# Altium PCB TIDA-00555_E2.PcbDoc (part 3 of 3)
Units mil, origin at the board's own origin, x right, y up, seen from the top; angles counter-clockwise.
Board outline 6490 x 3985 mil, 4 copper layers (Top Layer, MidLayer1, MidLayer2, Bottom Layer), stack 61.2 mil thick; 376 components, 194 nets, 936 pads, 294 vias.
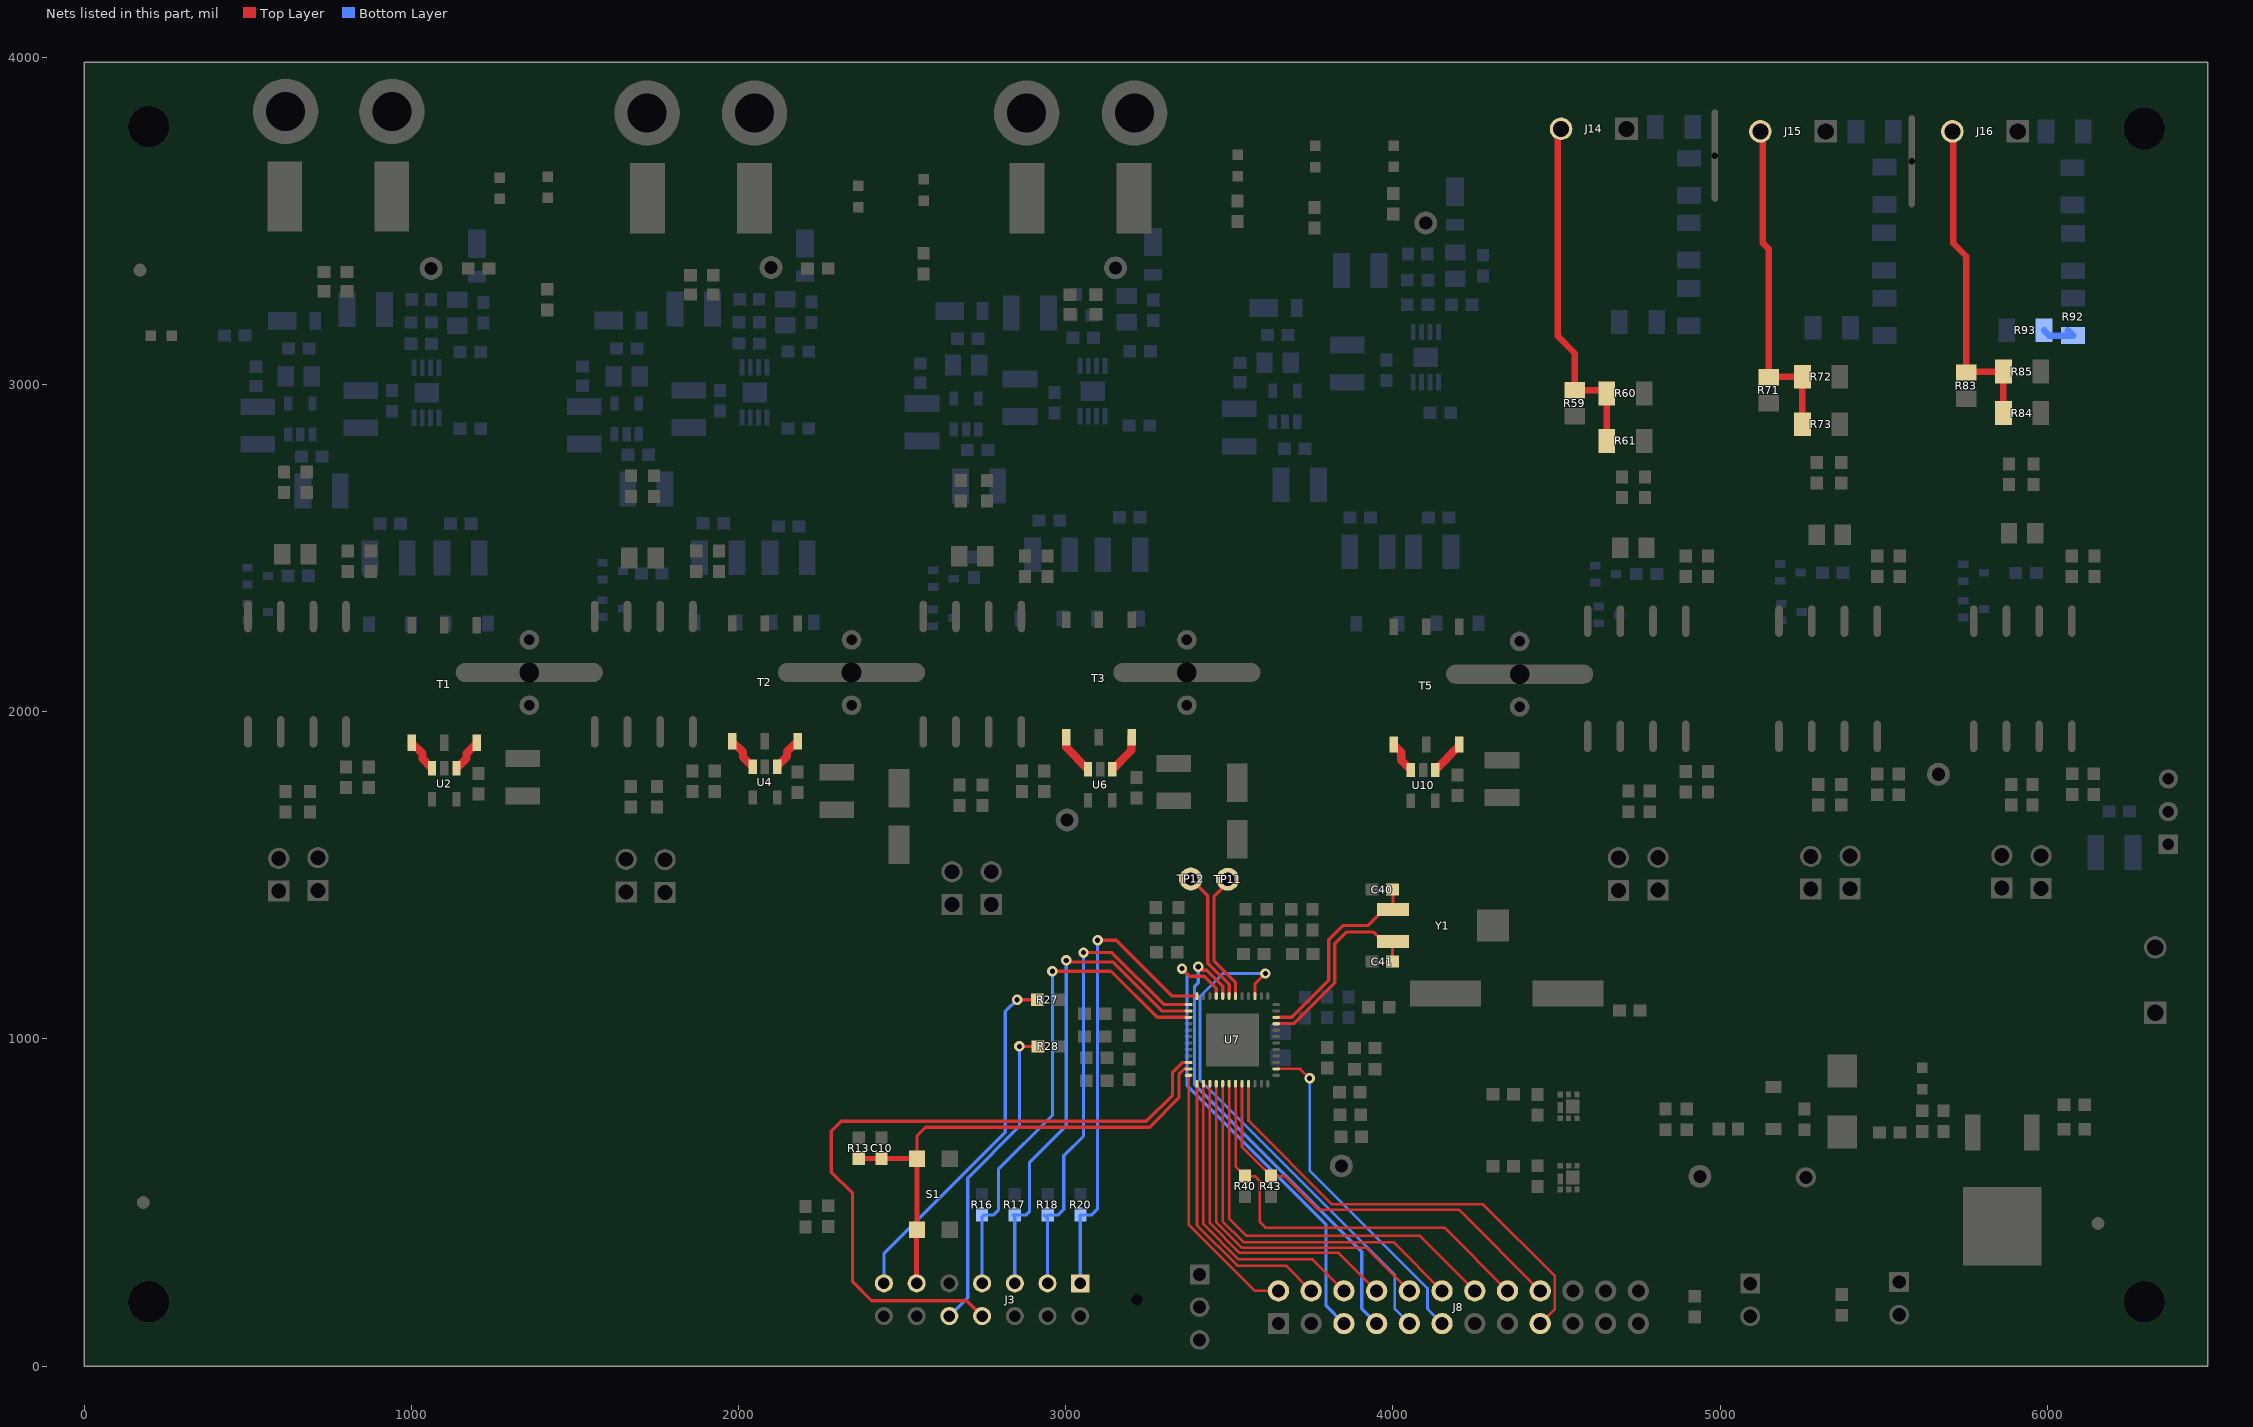
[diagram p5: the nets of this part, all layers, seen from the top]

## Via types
v1: diameter 32, hole 16, Top Layer to Bottom Layer, tented both sides, 177 vias
v2: diameter 40, hole 20, Top Layer to Bottom Layer, tented both sides, 109 vias
v3: diameter 19.68, hole 7.87, Top Layer to Bottom Layer, tented both sides, 8 vias

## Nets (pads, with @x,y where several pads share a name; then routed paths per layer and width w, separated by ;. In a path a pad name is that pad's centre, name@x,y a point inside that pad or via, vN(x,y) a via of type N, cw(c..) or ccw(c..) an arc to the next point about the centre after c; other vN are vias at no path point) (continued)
NetR92_2: R92.2 R93.1 | length 118.3
  Bottom Layer w20: R93.1@5990.09,3166 6006.17,3149.91 R92.2@6079,3149.91 R92.2@6062.91,3166
NetT1_1: T1.1 U2.3 | length 103.7
  Top Layer w25: T1.1@1000,1905 1033,1872 1033,1856.84 U2.3@1062.6,1827.24
NetT1_3: T1.3 U2.1 | length 103.7
  Top Layer w25: U2.1@1137.4,1827.24 1168,1857.84 1168,1873 T1.3@1200,1905
NetT2_1: T2.1 U4.3 | length 103.7
  Top Layer w25: T2.1@1980,1910 2013,1877 2013,1861.84 U4.3@2042.6,1832.24
NetT2_3: T2.3 U4.1 | length 103.7
  Top Layer w25: U4.1@2117.4,1832.24 2148,1862.84 2148,1878 T2.3@2180,1910
NetT3_1: T3.1 U6.3 | length 125.8
  Top Layer w25: T3.1@3000,1922 3000,1891.84 U6.3@3067.6,1824.24
NetT3_3: T3.3 U6.1 | length 121.6
  Top Layer w25: U6.1@3142.4,1824.24 3200,1881.84 T3.3@3200,1922
NetT5_1: T5.1 U10.3 | length 99.5
  Top Layer w25: T5.1@4002,1900.22 4025,1877.22 4025,1852.07 U10.3@4054.6,1822.47
NetT5_3: T5.3 U10.1 | length 107.8
  Top Layer w25: U10.1@4129.4,1822.47 4202,1895.07 T5.3@4202,1900.22
NetTP11_1: TP11.1 U7.6 | length 398.7
  Top Layer w10: TP11.1@3500,1483 3453,1436 3453,1238.17 3518.84,1172.33 U7.6@3518.84,1131.01
NetTP12_1: TP12.1 U7.7 | length 406.5
  Top Layer w10: TP12.1@3382,1489 3434,1437 3434,1231.71 3499.16,1166.56 U7.7@3499.16,1131.01
NEUTRAL: J14.2 J15.2 J16.2 R59.1 R60.1 R61.1 R71.1 R72.1 R73.1 R83.1 R84.1 R85.1 | length 3053.5
  Top Layer w20: J14.2@4513.72,3782 4503.72,3772 4503.72,3148.28 4555.72,3096.28 R59.1@4555.72,2983 4643.64,2983 R60.1@4653.64,2973 R61.1@4653.64,2828 ; J15.2@5122.72,3774 5129.72,3767 5129.72,3434 5148.72,3415 R71.1@5148.72,3023 5149.72,3024 R72.1@5251.64,3024 R73.1@5251.64,2879 ; J16.2@5709.72,3749 5712.72,3746 5712.72,3432 5752,3392.72 R83.1@5752,3037 5755,3040 R85.1@5865.91,3040 R84.1@5865.91,2913
P1.2: J8.9 U7.3 | length 1576.4
  Top Layer w10: U7.3@3577.9,1131.01 3577.9,1167.9 v1(3610,1200)
  Bottom Layer w8: v1(3610,1200) 3480,1200 3410,1130 3410,874 4005.52,278.48 4005.52,174.48 J8.9@4050,130
P1.3: J8.5 U7.9 | length 1443.7
  Top Layer w10: v1(3355,1215) 3378.18,1191.82 3422.99,1191.82 3459.79,1155.02 U7.9@3459.79,1131.01
  Bottom Layer w10: v1(3355,1215) 3370,1200 3370,858 3795.48,432.52 3795.48,184.52 J8.5@3850,130
P2.0: J8.2 U7.24 | length 814.7
  Top Layer w8: U7.24@3375.14,888.88 3375.14,795 3375.14,433.23 3578.37,230 J8.2@3650,230
P2.1: J8.4 U7.25 | length 865.2
  Top Layer w8: U7.25@3400.73,863.29 3400.73,430.27 3524,307 3673,307 J8.4@3750,230
P2.2: J8.6 U7.26 | length 943.5
  Top Layer w8: U7.26@3420.42,863.29 3420.42,433.7 3528.12,326 3754,326 J8.6@3850,230
P2.7: J8.11 U7.38 | length 1031.7
  Top Layer w8: U7.38@3642.86,908.57 3716.43,908.57 v1(3745,880)
  Bottom Layer w8: v1(3745,880) 3745,597.9 4105.52,237.38 4105.52,174.48 J8.11@4150,130
P3.4: J8.8 U7.27 | length 1022.1
  Top Layer w8: U7.27@3440.1,863.29 3440.1,436.64 3530.75,346 3834,346 J8.8@3950,230
P3.5: J8.10 U7.28 | length 1100.7
  Top Layer w8: U7.28@3459.79,863.29 3459.79,439.59 3537.37,362 3918,362 J8.10@4050,230
P3.6: J8.12 U7.29 | length 1179.3
  Top Layer w8: U7.29@3479.47,863.29 3479.47,442.53 3543,379 4001,379 J8.12@4150,230
P3.7: J8.14 U7.30 | length 1254.8
  Top Layer w8: U7.30@3499.16,863.29 3500,862.45 3500,450 3551,399 4081,399 J8.14@4250,230
P4.4: J8.17 U7.33 | length 1410
  Top Layer w8: U7.33@3558.21,863.29 3558.21,750 3814,494.21 4275.79,494.21 4494.48,275.52 4494.48,174.48 J8.17@4450,130
P4.7: J8.7 U7.8 | length 1456.5
  Top Layer w10: v1(3405,1221) 3405,1220 3415.18,1209.82 3430.44,1209.82 3479.47,1160.79 U7.8@3479.47,1131.01
  Bottom Layer w10: v1(3405,1221) 3405,1172.13 3393,1160.13 3393,861 3904.52,349.48 3904.52,175.48 J8.7@3950,130
RESET: C10.1 J3.11 R13.1 S1.1 S1.2 U7.23 | length 1590.9
  Top Layer w10: S1.1@2545,637 2545,704 2571,730 3256,730 3345.55,819.55 3345.55,891.45 3362.67,908.57 U7.23@3375.14,908.57
  Top Layer w15: R13.1@2366.76,634.24 C10.1@2436.76,634.24 S1.1@2548.03,634.24 ; J3.11@2543,254 J3.11@2544,253 2544,415.73 S1.2@2545,416.73 2545,631.2 S1.1@2548.03,634.24 ; S1.1@2549,633.27 S1.1@2548.03,634.24
SCL: J8.18 R43.2 U7.32 | length 1287.6
  Top Layer w8: U7.32@3538.53,863.29 3538.53,668.97 R43.2@3627,580.5 3668.5,580.5 3770.79,478.21 4201.79,478.21 J8.18@4450,230
SDA: J8.16 R40.2 U7.31 | length 1315.3
  Top Layer w8: U7.31@3518.84,863.29 3518.84,609.65 R40.2@3548,580.5 3577.5,580.5 3593,565 3593,440 3610,423 4157,423 J8.16@4350,230
TCK: J3.7 R16.2 U7.15 | length 1535
  Top Layer w10: v1(2959,1207) 3138,1207 3278.95,1066.05 U7.15@3375.14,1066.05
  Bottom Layer w10: J3.7@2744,253 2744,456.5 2749,461.5 2778.7,461.5 2794,476.8 2794,601 2959,766 v1(2959,1207)
TDI: J3.3 R18.2 U7.13 | length 1465.4
  Top Layer w10: v1(3054,1264) 3141,1264 3299.58,1105.42 U7.13@3375.14,1105.42
  Bottom Layer w10: R18.2@2934,461.5 2944,451.5 J3.3@2944,253 ; R18.2@2945,462 2977,462 2994,479 2994,643 3054,703 v1(3054,1264)
TDO: J3.1 R20.2 U7.12 | length 1466
  Top Layer w10: v1(3097,1302) 3154.01,1302 3325,1131.01 U7.12@3400.73,1131.01
  Bottom Layer w10: J3.1@3044,253 3044,460.5 R20.2@3045,461.5 3077.5,461.5 3097,481 v1(3097,1302) v1@3096,1301
TEST/SBWTCK: J3.8 U7.22 | length 2146.3
  Top Layer w10: J3.8@2744,153 2697,200 2406,200 2348,258 2348,528 2283,593 2283,718 2313,748 3246,748 3326.33,828.33 3326.33,897.67 3356.9,928.25 U7.22@3375.14,928.25
TMS: J3.5 R17.2 U7.14 | length 1516.8
  Top Layer w10: v1(3001,1240) 3006,1235 3144.54,1235 3293.81,1085.73 U7.14@3375.14,1085.73
  Bottom Layer w10: J3.5@2844,253 2844,456.5 2839,461.5 2877.5,461.5 2889,473 2889,623 3001,735 v1(3001,1240)
UART_CTS: J3.10 R28.1 | length 969.1
  Top Layer w10: v1(2858,977) R28.1@2914.5,977
  Bottom Layer w10: J3.10@2644,153 2700,209 2700,574.51 2858,732.51 v1(2858,977)
UART_RTS: J3.13 R27.1 | length 1097.1
  Top Layer w10: v1(2851,1120) R27.1@2912.5,1120
  Bottom Layer w10: J3.13@2444,253 2444,343.96 2815,714.96 2815,1084 v1(2851,1120)
XIN: C41.1 U7.45 Y1.2 | length 617.1
  Top Layer w10: U7.45@3642.86,1046.36 3643.5,1047 3697.01,1047 3822.23,1172.22 3822.23,1291.23 3858,1327 3940,1327 3969.66,1297.34 Y1.2@4000.26,1297.34 3998.61,1295.68 C41.1@3998.61,1236.55
XOUT: C40.1 U7.46 Y1.1 | length 627.8
  Top Layer w10: U7.46@3642.86,1066.05 3690.59,1066.05 3804,1179.45 3804,1303 3848,1347 3925,1347 3973.76,1395.76 Y1.1@4000.26,1395.76 4000.26,1454.9 C40.1@3998.61,1456.55
pads on no net: FID1.1 FID2.1 FID3.1 FID4.1 FID5.1 FID6.1 J3. J3.6 J8.1 J8.3 J8.13 J8.15 J8.19 J8.20 LBL1.0 MH1.1 MH2.1 MH3.1 MH4.1 T1.5 T2.5 T3.5 T5.5 U15.7 U16.4 U16.5 U19.7 U20.4 U20.5 U21.7 U22.4 U22.5 U23.7 U24.4 U24.5
copper on no net: | length 6498
  Top Layer w8: 535,110 535,210 ; 635,110 635,210 ; 735,110 735,210 ; 435,110 435,210 835,210 835,110 435,110
  MidLayer1 w8: 435,110 835,110 ; 435,110 435,210 ; 435,110 435,210 ; 435,110 835,110 ; 435,210 835,210 ; 435,210 835,210 ; 835,110 835,210 ; 835,110 835,210 ; 535,110 535,210 535,110 ; 635,110 635,210 635,110 ; 735,110 735,210 735,110
  MidLayer2 w8: 535,110 535,210 ; 635,110 635,210 ; 735,112 735,210 ; 435,110 835,110 835,210 435,210 435,110
  Bottom Layer w8: 535,110 535,210 ; 635,110 635,210 ; 735,110 735,210 ; 435,110 835,110 835,210 435,210 435,110

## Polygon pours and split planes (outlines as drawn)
GND_PH on MidLayer1 "Bottom Layer-No Net 1" (solid, remove dead copper, pour order 118): 3651,2254 3490,2415 3490,3125 3680,3315 3680,3865 3740,3925 4267,3925 4319,3878 4318,3879 4318.24,3925 4318.24,3142.76 4366,3095 6480,3095 6478.24,2270 6460.4,2254
GND_WSH on MidLayer1 "Top Layer-No Net" (solid, remove dead copper, pour order 88): 2535,3375 2430,3270 2430,2415 2560,2285 3340,2285 3342,2287 3342,2290 3341.81,3241.81 3415,3315 3515,3315 3610,3410 3610,3905 3600,3915 3505,3915 3495,3905 3495,3445 3460,3410 2970,3410 2935,3445 2935,3720 2975,3760 2975,3905 2940,3940 2590,3940 2535,3885
GND_VSH on MidLayer1 "Top Layer-No Net" (solid, remove dead copper, pour order 84): 1400,2605 1500,2505 1500,2345 1570,2275 2315,2275 2320,2280 2320,3250 2455,3385 2455,3925 2440,3940 2345,3940 2335,3930 2335,3450 2300,3415 1810,3415 1785,3440 1785,3705 1840,3760 1840,3910 1808.24,3941.76 1446.76,3941.76 1400,3895
GND_USH on MidLayer1 "Top Layer-No Net" (solid, remove dead copper, pour order 80): 130,3940 75,3885 75,2365 170,2270 1305,2270 1330,2295 1330,3910 1310,3930 1230,3930 1215,3915 1215,3440 1195,3420 715,3420 665,3470 665,3710 725,3770 725,3900 685,3940
DGND on MidLayer1 "Bottom Layer-No Net 1" (solid, remove dead copper, pour order 98): 20,1870 125,1975 6333,1975 6422,1886 6422,107 6335,20 180,20 20,180
NEUTRAL on MidLayer1 "Bottom Layer-No Net 1" (solid, remove dead copper, pour order 119): 4408.2,3930.2 4448,3970 6015,3970 6025,3960 6025,3850 6013,3837 5813.45,3836.95 5777,3800.5 5777,3591.97 5735.53,3550.5 5651.65,3550.5 5618,3584.15 5618,3843 5593,3868 5269.5,3868 5227,3825.5 5227,3575.5 5202,3550.5 5052,3550.5 5032,3570.5 5032,3842 4999,3875 4676.5,3875 4627,3825.5 4627,3600.5 4577,3550.5 4433,3550 4410,3550 4408.2,3550.5
+5.0V_PH on MidLayer2 "Bottom Layer-No Net 1" (solid, remove dead copper, pour order 117): 3650,2255 3490,2415 3490,3120 3680,3310 3680,3860 3740,3920 4265,3920 4318,3867 4318,3192 4319,3145 4343,3121 4363.71,3097.29 4391,3097 6478.98,3097 6478.23,2255
+5.0V_WSH on MidLayer2 "Top Layer-No Net" (solid, remove dead copper, pour order 87): 2540,3370 2435,3265 2435,2410 2560,2285 3345,2285 3347,2287 3347,2294 3346.81,3236.81 3420,3310 3520,3310 3615,3405 3615,3900 3605,3910 3510,3910 3500,3900 3500,3440 3465,3405 2975,3405 2940,3440 2940,3715 2980,3755 2980,3900 2945,3935 2595,3935 2540,3880
+5.0V_VSH on MidLayer2 "Top Layer-No Net" (solid, remove dead copper, pour order 83): 1400,2600 1500,2500 1500,2345 1570,2275 2290,2275 2320,2305.11 2320,3245 2455,3380 2455,3920 2440,3935 2345,3935 2335,3925 2335,3445 2300,3410 1810,3410 1785,3435 1785,3700 1840,3755 1840,3905 1808.24,3936.76 1446.76,3936.76 1400,3890
+5.0V_USH on MidLayer2 "Top Layer-No Net" (solid, remove dead copper, pour order 79): 130,3940 75,3885 75,2395 200,2270 1305,2270 1330,2295 1330,3910 1310,3930 1230,3930 1215,3915 1215,3440 1195,3420 715,3420 665,3470 665,3710 725,3770 725,3900 685,3940
AVCC on MidLayer2 "Top Layer-No Net" (solid, remove dead copper, pour order 70): 6405,1630 6441.76,1593.24 6441.76,1302.35 6399.41,1260 5760,1260 5710,1210 5710.2,689.02 5670,650 4594.18,650 4174.18,1020 130,1020 60,1090 60,1570 120,1630
DVCC on MidLayer2 "Bottom Layer-No Net 1" (solid, remove dead copper, pour order 100): 135,20 20,135 20,875 120,975 4125,975 4485,615 5690,615 5749,674 5749,1159 5785,1195 6390,1195 6415,1170 6415,20
AMC_VCC on MidLayer2 "Top Layer-No Net" (solid, remove dead copper, pour order 73): 6422,1660.47 6440,1670 6440,1950 6420,1970 120,1970 60,1910 60,1720 120,1660
+5.0V_PH on Bottom Layer "Bottom Layer-No Net 2" (solid, remove dead copper, pour order 133): 4254,3370 4254,3470 4273.2,3489.2 4273.2,3493.48 4315.52,3493.48 4350,2570 4350,2500 4370,2520 6004,2520 6079,2445 6079,2295 6004,2220 4579,2220 4350,2460 4354,3320 4304,3370
+5V_CNTL on Bottom Layer "Top Layer-No Net" (solid, remove dead copper, pour order 69): 6420,1970 6440,1950 6440,1024.72 6400,984.72 5975.28,984.72 5950,1010 5950,1300 5905,1345 75,1345 50,1370 50,1890 135,1975
AGND on Bottom Layer "Bottom Layer-No Net 2" (solid, remove dead copper, pour order 120): 5880,1295 5895,1280 5895,700 5900,695 6470,695 6470,65 6430,25 144.94,20 20,144.94 25,1295
+6V_PH on Bottom Layer "Bottom Layer-No Net 1" (solid, remove dead copper, pour order 95): 3837.32,2202.15 3897.32,2202.15 3897,2381 3897,2650 3890,2657 3813,2657 3807,2651 3807,2621 3798,2612 3692.32,2612.15 3677.32,2627.15 3677.32,2822.15 3667.32,2832.15 3622.32,2832.15 3612.32,2812.15 3612.32,2562.15 3647.32,2522.15 3707.32,2522.15 3827.32,2397.15 3827.32,2217.15
+6V_WSH on Bottom Layer "Bottom Layer-No Net 1" (solid, remove dead copper, pour order 74): 2861.98,2261 2876.98,2246 2927.98,2246 2940.98,2262 2941.61,2331 2942,2467 2942,2614 2940,2616 2866,2616 2865,2615 2861.61,2611 2851.61,2601 2756.61,2601 2716.61,2641 2716.61,2811 2701.61,2826 2701.61,2871 2681.61,2871 2681.61,2831 2626.61,2776 2626.61,2631 2726.61,2531 2806.61,2531 2861.61,2491 2861.61,2341
+6V_VSH on Bottom Layer "Bottom Layer-No Net 1" (solid, remove dead copper, pour order 75): 1828,2256 1843,2241 1896,2241 1910,2255 1910,2610 1847,2610 1828,2596 1722.64,2596 1682.64,2636 1682.64,2806 1667.64,2821 1667.64,2866 1647.64,2866 1647.64,2826 1592.64,2771 1592.64,2626 1678.64,2540 1796.62,2540 1827.64,2517.45 1827.64,2336
GND_WSH on Bottom Layer "Bottom Layer-No Net 1" (solid, remove dead copper, pour order 91): 2976.61,2406 3136.61,2406 3156.61,2426 3156.61,2646 3141.61,2661 2971.61,2661 2961.61,2651 2961.61,2421
GND_VSH on Bottom Layer "Bottom Layer-No Net 1" (solid, remove dead copper, pour order 92): 1940,2415 2100,2415 2120,2435 2120,2655 2105,2670 1935,2670 1925,2660 1925,2430
GND_USH on Bottom Layer "Bottom Layer-No Net 1" (solid, remove dead copper, pour order 93): 960,2415 1120,2415 1140,2435 1140,2655 1125,2670 955,2670 945,2660 945,2430
+6V_USH on Bottom Layer "Bottom Layer-No Net 1" (solid, remove dead copper, pour order 96): 825,2248 835,2240 910,2240 920,2249 920,2625 845,2625 840,2620 840,2600 835,2595 735,2595 690,2640 690,2790 670,2810 670,2865 665,2870 646.65,2870 646.65,2831.65 645,2830 645,2805 600,2760 600,2615 685,2530 760,2530 825,2465
-5.0V_WSH on Bottom Layer "Bottom Layer-No Net 1" (solid, remove dead copper, pour order 112): 3082,3250 3072,3260 3072,3380 3072,3390 3097,3415 3099,3417 3160,3417 3172,3417 3183,3406 3188,3401 3188,3376 3188,3368 3196,3360 3200,3356 3244,3356 3282,3356 3288,3350 3296,3342 3296,3285 3296,3255 3278,3237 3276,3235 3120,3235 3098,3235 3082,3251
-5.0V_USH on Bottom Layer "Bottom Layer-No Net 1" (solid, remove dead copper, pour order 111): 1035,3290 1005,3320 1005,3390 1040,3425 1115,3425 1130,3410 1130,3370 1145,3355 1225,3355 1275,3300 1275,3250 1250,3225 1050,3225 1035,3232.31
-6V_VSH on Bottom Layer "Bottom Layer-No Net 1" (solid, remove dead copper, pour order 78): 2168,2259 2185,2243 2255,2243 2273,2254.33 2273,2301 2272.64,2336 2272.64,2741 2217.64,2796 2087.64,2796 2082.64,2831 2037.64,2836 2017.64,2866 2017.64,2921 2002.64,2936 1797.64,2936 1772.64,2911 1772.64,2826 1837.64,2736 2142.64,2736 2162.64,2721 2162.64,2716 2167.64,2711 2167.64,2346
NetD37_1 on Bottom Layer "Bottom Layer-No Net 1" (solid, remove dead copper, pour order 89): 1960,2240 1960,2300 1971,2311 1971,2314 2110,2314 2116,2308 2120,2304 2120,2269 2120,2242 2112,2234 2108,2230 1970,2230 1960,2240
-6V_USH on Bottom Layer "Bottom Layer-No Net 1" (solid, remove dead copper, pour order 94): 1181,2232 1284,2232 1323,2268 1321,2579 1286,2614 1270,2631 1270,2765 1230,2805 1041,2805 1015,2831 1015,2925 1000,2940 910,2940 880,2910 790,2910 775,2895 775,2835 855,2755 1160,2755 1185,2730 1185,2635 1160,2610 1160,2335 1180,2306.57
GND_VSH on Bottom Layer "Bottom Layer-No Net 1" (solid, remove dead copper, pour order 102): 1472.64,2846 1562.64,2846 1577.64,2846 1582.64,2841 1582.64,2791 1582.64,2726 1572.64,2716 1487.64,2716 1482.64,2716 1472.64,2726 1472.64,2846
GND_USH on Bottom Layer "Bottom Layer-No Net 1" (solid, remove dead copper, pour order 103): 475,2845 565,2845 580,2845 585,2840 585,2790 585,2725 575,2715 490,2715 485,2715 475,2725 475,2845
GND_USH on Bottom Layer "Bottom Layer-No Net 1" (solid, remove dead copper, pour order 97): 745,2615 746.72,2613.28 816.2,2613.28 816.2,2736.72 815,2737.92 815,2755 815,2760 755,2820 750,2825 750,2855 750,2910 785,2945 795,2955 950,2955 1000,2955 1010,2945 1015,2940 1080,2940 1120,2940 1155,2975 1235,2975 1250,2975 1280,3005 1290,3015 1290,3145 1290,3185 1260,3215 1150,3215 1110,3215 1105,3210 1100,3205 1100,3170 1100,3161 1115,3146 1180,3146 1184,3146 1190,3140 1195,3135 1195,3090 1195,3080 1175,3060 1170,3055 1115,3055 1095,3075 1055,3075 1050,3070 1050,3025 1050,3020 1045,3015 960,3015 895,3015 860,3050 855,3055 855,3265 855,3275 835,3295 730,3295 700,3295 680,3275 665,3260 665,3080 665,2995 680,2980 685,2975 705,2975 710,2975 720,2965 721.03,2963.97 721.03,2885.16 720.16,2885.16 715,2880 695,2880 690,2880 688.29,2878.29 688.29,2870 688.29,2831.71 690,2830 710,2810 710,2770 710,2650 745,2615
GND_VSH on Bottom Layer "Bottom Layer-No Net 1" (solid, remove dead copper, pour order 85): 1737.64,2626 1798.84,2626 1802.64,2631 1802.64,2760.98 1747.64,2815.98 1747.64,2936 1767.64,2956 2137.64,2956 2147.64,2966 2262.64,2966 2302.64,3006 2302.64,3181 2272.64,3211 2117.64,3211 2107.64,3201 2107.64,3166 2122.64,3151 2187.64,3151 2197.64,3141 2197.64,3071 2192.64,3066 2122.64,3066 2102.64,3086 2052.64,3086 2052.64,3026 2037.64,3011 1882.64,3011 1852.64,3041 1852.64,3276 1832.64,3296 1767.64,3296 1757.64,3286 1757.64,3251 1732.64,3226 1682.64,3226 1672.64,3216 1672.64,2891 1682.64,2881 1682.64,2826 1707.64,2801 1707.64,2656
-5.0V_VSH on Bottom Layer "Bottom Layer-No Net 1" (solid, remove dead copper, pour order 113): 2045,3244 2035,3254 2035,3374 2035,3384 2060,3409 2062,3411 2123,3411 2135,3411 2146,3400 2151,3395 2151,3370 2151,3362 2159,3354 2163,3350 2207,3350 2245,3350 2251,3344 2259,3336 2259,3279 2259,3249 2241,3231 2239,3229 2083,3229 2061,3229 2045,3245
NetD21_1 on Bottom Layer "Bottom Layer-No Net 1" (solid, remove dead copper, pour order 115): 3971.5,2236 3971.5,2311 3981.5,2321 3986.5,2326 4076.5,2326 4144,2326 4156.5,2313.5 4156.5,2246 4156.5,2231 4146.5,2221 3986.5,2221 3971.5,2236
GND_PH on Bottom Layer "Bottom Layer-No Net 1" (solid, remove dead copper, pour order 108): 3955,2439 4090,2439 4130,2479 4130,2719 4117.05,2737 3937.05,2737 3925.05,2717 3925,2679 3925,2469
GND_PH on Bottom Layer "Bottom Layer-No Net 1" (solid, remove dead copper, pour order 99): 3475,2839 3565,2839 3580,2839 3585,2834 3585,2784 3585,2719 3575,2709 3490,2709 3485,2709 3475,2719 3475,2839
GND_PH on Bottom Layer "Bottom Layer-No Net 1" (solid, remove dead copper, pour order 110): 3752.95,2629 3725,2649 3725,2774 3710,2794 3710,2829 3700,2849 3700,2894 3727.95,2894 3722.94,3144 3767.95,3144 3767.95,2899 3822.95,2834 3822.95,2639 3812.95,2629
-6V_PH on Bottom Layer "Bottom Layer-No Net 1" (solid, remove dead copper, pour order 90): 4230,2199 4310,2199 4305,2349 4255,2399 4255,2814 4220,2834 4080,2834 4055,2859 4055,2919 4070,2974 4070,3029 3805,3029 3795,2974 3795,2899 3935,2754 4130,2754 4150,2734 4150,2354 4230,2274.8
-5.0V_PH on Bottom Layer "Bottom Layer-No Net 1" (solid, remove dead copper, pour order 114): 4081.2,3454.48 4077.2,3458.48 4077.2,3515.48 4077.2,3517.48 4087.2,3527.48 4089.2,3529.48 4151.2,3529.48 4170.2,3529.48 4200.2,3499.48 4206.2,3493.48 4268.2,3493.48 4273.2,3493.48 4290.2,3476.48 4302.2,3464.48 4302.2,3383.48 4302.2,3380.48 4293.2,3371.48 4292.2,3370.48 4100.2,3370.48 4100.2,3371.48 4087.2,3384.48 4087.2,3440.48 4087.2,3448.48 4081.2,3454.48
GND_PH on Bottom Layer "Bottom Layer-No Net 1" (solid, remove dead copper, pour order 109): 3780,3009 3712.95,3009 3665,3034 3665,3234 3685,3254 3792.95,3254 3812.95,3274 3812.95,3414 3827.95,3429 3887.95,3429 3897.95,3419 3897.95,3189 3942.95,3144 4102.95,3144 4102.95,3209 4232.95,3209 4232.95,3274 4227.95,3280 4226.95,3279 4221.95,3284 4162.95,3284 4152.95,3294 4152.95,3339 4157.95,3344 4257.95,3344 4295,3344 4302.2,3330 4300,3179 4220,3119 4125,3054 4045,3054 4035,3049 3795,3049 3779.23,3035
NetD32_1 on Bottom Layer "Bottom Layer-No Net 1" (solid, remove dead copper, pour order 86): 2965,2255 2965,2315 2976,2326 2976,2329 3115,2329 3121,2323 3125,2319 3125,2284 3125,2257 3117,2249 3113,2245 2975,2245 2965,2255
GND_WSH on Bottom Layer "Bottom Layer-No Net 1" (solid, remove dead copper, pour order 101): 2510,2855 2600,2855 2615,2855 2620,2850 2620,2800 2620,2735 2610,2725 2525,2725 2520,2725 2510,2735 2510,2855
-6V_WSH on Bottom Layer "Bottom Layer-No Net 1" (solid, remove dead copper, pour order 77): 3207.86,2268 3224.86,2252 3294.86,2252 3312.86,2263.33 3312.86,2310 3312.5,2345 3312.5,2750 3260.89,2804 3160.89,2804 3115.89,2849 3075.89,2849 3060.89,2864 3060.89,2934 3050.89,2944 2837.5,2945 2812.5,2920 2812.5,2835 2877.5,2745 3182.5,2745 3202.5,2730 3202.5,2725 3207.5,2720 3207.5,2355
GND_WSH on Bottom Layer "Bottom Layer-No Net 1" (solid, remove dead copper, pour order 82): 2776.81,2623.72 2838.01,2623.72 2841.81,2628.72 2841.81,2758.7 2786.81,2813.7 2786.81,2933.72 2806.81,2953.72 3176.81,2953.72 3186.81,2963.72 3301.81,2963.72 3341.81,3003.72 3341.81,3178.72 3311.81,3208.72 3156.81,3208.72 3146.81,3198.72 3146.81,3163.72 3161.81,3148.72 3226.81,3148.72 3236.81,3138.72 3236.81,3068.72 3231.81,3063.72 3161.81,3063.72 3140,3085 3095,3085 3085,3075 3085,3020 3076.81,3008.72 2921.81,3008.72 2891.81,3038.72 2891.81,3273.72 2875,3290 2800,3290 2795,3285 2795,3275 2785,3265 2745,3265 2725.22,3264.94 2710,3245 2710,2890 2721.81,2878.72 2721.81,2823.72 2746.81,2798.72 2746.81,2653.72
GND_USH on Bottom Layer "Bottom Layer-No Net 2" (solid, remove dead copper, pour order 132): 345,3510 400,3455 650,3455 665,3470 665,3700 740,3775 740,3900 680,3960 410,3960 345,3895
GND_VSH on Bottom Layer "Bottom Layer-No Net 2" (solid, remove dead copper, pour order 131): 1465,3495 1520,3440 1770,3440 1785,3455 1785,3685 1860,3760 1860,3885 1800,3945 1530,3945 1465,3880
GND_WSH on Bottom Layer "Bottom Layer-No Net 2" (solid, remove dead copper, pour order 130): 2615,3485 2670,3430 2920,3430 2935,3445 2935,3675 3010,3750 3010,3875 2950,3935 2680,3935 2615,3870
NetFB6_1 on Bottom Layer "Bottom Layer-No Net 2" (solid, remove dead copper, pour order 126): 3470,3535 3450,3515 3160,3515 3150,3525 3150,3690 3075,3765 3075,3895 3120,3940 3400,3940 3470,3870
NetFB4_1 on Bottom Layer "Bottom Layer-No Net 2" (solid, remove dead copper, pour order 125): 2315,3535 2290,3510 2030,3510 2010,3520 1995,3535 1995,3700 1920,3775 1920,3905 1965,3950 2245,3950 2315,3880
NetFB2_1 on Bottom Layer "Bottom Layer-No Net 2" (solid, remove dead copper, pour order 124): 1205,3565 1100,3460 900,3460 885,3475 885,3705 810,3780 810,3910 855,3955 1135,3955 1205,3885
GND_WSH on Top Layer "Bottom Layer-No Net 1" (solid, remove dead copper, pour order 104): 3175,2238 3285,2238 3315,2272 3315,2447 3175,2587 3175,2672 3150,2697 2970,2697 2955,2682 2955,2612 3175,2392
GND_PH on Top Layer "Bottom Layer-No Net 1" (solid, remove dead copper, pour order 105): 4156.5,2231 4266.5,2231 4296.5,2265 4296.5,2440 4156.5,2580 4156.5,2665 4131.5,2690 3951.5,2690 3936.5,2675 3936.5,2605 4156.5,2385
GND_VSH on Top Layer "Bottom Layer-No Net 1" (solid, remove dead copper, pour order 106): 2165,2231 2275,2231 2305,2265 2305,2440 2165,2580 2165,2665 2140,2690 1960,2690 1945,2675 1945,2605 2165,2385
GND_USH on Top Layer "Bottom Layer-No Net 1" (solid, remove dead copper, pour order 107): 1180,2241 1290,2241 1320,2275 1320,2450 1180,2590 1180,2675 1155,2700 975,2700 960,2685 960,2615 1180,2395
+5V_CNTL on Top Layer "Top Layer-No Net" (solid, remove dead copper, pour order 134): 5930,625 6060,625 6075,640 6075,960 6120,1005 6395,1005 6415,1025 6415,1150 6390,1175 5920,1175 5895,1150 5895,660
AVCC on Top Layer "Bottom Layer-No Net 1" (solid, remove dead copper, pour order 81): 5016.5,646 5016.5,751 5006.5,761 4956.5,761 4941.5,751 4806.5,751 4791.5,736 4791.5,646.5 4896.66,541.34 5017,541
DVCC on Top Layer "Top Layer-No Net" (solid, remove dead copper, pour order 72): 5509,771 5509,661 5509,566 5469,526 5064,526 5059,526 5034,551 5034,756 5039,761 5042,764 5097,764 5111,764 5129,746 5134,741 5299,741 5324,766 5334,776 5489,776 5509,756
NetC63_1 on Top Layer "Bottom Layer-No Net 1" (solid, remove dead copper, pour order 76): 5802.7,657.5 5802.7,767.5 5792.7,777.5 5747.7,777.5 5742.7,777.5 5732.7,767.5 5727.7,762.5 5727.7,747.5 5717.7,737.5 5687.7,737.5 5532.7,737.5 5527.7,732.5 5527.7,682.5 5537.7,672.5 5562.7,647.5 5722.7,647.5 5792.7,647.5 5802.7,657.5
NetD12_1 on Top Layer "Bottom Layer-No Net 1" (solid, remove dead copper, pour order 71): 4530,742 4527,745 4527,841 4527,846 4537,856 4577,856 4587,846 4597,836 4597,771 4597,741 4592,736 4537,736 4527,746
NetD21_1 on Top Layer "Bottom Layer-No Net 1" (solid, remove dead copper, pour order 116): 3981.5,2328 4074.5,2328 4083.5,2319 4086.5,2316 4086.5,2243 4086.5,2233 4076.5,2223 3996.5,2223 3981.5,2223 3966.5,2238 3966.5,2313 3981.5,2328
NetD10_1 on Top Layer "Top Layer-No Net" (solid, remove dead copper, pour order 68): 4540,630 4570,630 4580,620 4580,530 4570,520 4540,520 4530,530 4530,620 4540,630
GND_USH on Top Layer "Bottom Layer-No Net 2" (solid, remove dead copper, pour order 129): 345,3510 400,3455 650,3455 665,3470 665,3700 740,3775 740,3900 680,3960 410,3960 345,3895
GND_VSH on Top Layer "Bottom Layer-No Net 2" (solid, remove dead copper, pour order 128): 1465,3500 1520,3445 1770,3445 1785,3460 1785,3690 1860,3765 1860,3890 1800,3950 1530,3950 1465,3885
NetFB2_1 on Top Layer "Bottom Layer-No Net 2" (solid, remove dead copper, pour order 123): 1205,3465 900,3465 885,3480 885,3710 810,3785 810,3915 855,3960 1135,3960 1205,3890
NetFB4_1 on Top Layer "Bottom Layer-No Net 2" (solid, remove dead copper, pour order 122): 2315,3455 2010,3455 1995,3470 1995,3700 1920,3775 1920,3905 1965,3950 2245,3950 2315,3880
GND_WSH on Top Layer "Bottom Layer-No Net 2" (solid, remove dead copper, pour order 127): 2615,3490 2670,3435 2920,3435 2935,3450 2935,3680 3010,3755 3010,3880 2950,3940 2680,3940 2615,3875
NetFB6_1 on Top Layer "Bottom Layer-No Net 2" (solid, remove dead copper, pour order 121): 3470,3440 3165,3440 3150,3455 3150,3685 3075,3760 3075,3890 3120,3935 3400,3935 3470,3865

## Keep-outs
Keep-Out Layer:
  circle w8: c6296.32,196.85 r120
  circle w8: c196.8,196.8 r120
  circle w8: c196.85,3788.19 r120
  circle w8: c6296.32,3783.19 r120
  lines w6: 20,20 20,3970 6470,3970 6470,20 20,20

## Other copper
Top Layer:
  region net NetD32_1: 3071,2254 3061,2244 2986,2244 2976,2254 2976,2314 2986,2324 3061,2324 3071,2314
  region net NetD43_1: 1075,2235 1065,2225 990,2225 980,2235 980,2295 990,2305 1065,2305 1075,2295
  region net NetD37_1: 2055,2240 2045,2230 1970,2230 1960,2240 1960,2300 1970,2310 2045,2310 2055,2300
  text "1" at 475,135 h40
  text ".Layer_Name" at -243,-1588.49 h60
MidLayer1:
  text "2" at 573.3,141 h40
  text ".Layer_Name" at -243,-1588.49 h60
MidLayer2:
  text "3" at 674.3,141 h40
  text ".Layer_Name" at -243,-1588.49 h60
Bottom Layer:
  region net NetC111_2: 3052.5,3290 3052.5,3110 3047.5,3105 3047.5,3030 2952.5,3030 2922.5,3045 2922.5,3290
  region net +5.0V_USH: 470,3045 482,3033 542,3033 585,2990 650,2990 650,3225 490,3225 470,3205
  region net NetC143_2: 1020,3285 1020,3105 1015,3100 1015,3027 988,3027 975,3040 915,3040 890,3065 890,3285
  region net NetD43_1: 1111,2296.57 1111,2236.57 1101,2226.57 1001,2226.57 991,2236.57 991,2296.57 1001,2306.57 1101,2306.57
  pour cut-out: 688.29,2870 688.29,2911.71 690,2960 670,2980 605,2980 605,2870
  region net NetC153_2: 537,3018 595,2960 595,2915 635,2875 635,2825 610,2825 610,2855 595,2870 480,2870 470,2880 470,2995 493,3018
  region net NetC137_2: 1538.13,3015 1592.63,2960.5 1592.63,2915.5 1632.63,2875.5 1632.63,2825.5 1607.63,2825.5 1607.63,2855.5 1592.63,2870.5 1477.63,2870.5 1467.63,2880.5 1467.63,2995.5 1487.14,3015
  region net NetC127_2: 2022.64,3286 2022.64,3106 2017.64,3101 2017.64,3026 1922.64,3026 1892.64,3041 1892.64,3286
  region net +5.0V_VSH: 1467.63,3045.5 1477.13,3036 1537.13,3036 1582.63,2990.5 1647.63,2990.5 1647.63,3225.5 1487.63,3225.5 1467.63,3205.5
  region net NetC86_2: 3560.09,3029 3602.95,2994 3602.95,2949 3642.95,2909 3642.95,2859 3617.95,2859 3617.95,2889 3602.95,2904 3487.95,2904 3477.95,2914 3480,3014 3495,3029
  region net +5.0V_PH: 3457.95,3089 3470,3074 3490,3049 3555,3049 3572.95,3034 3637.95,3034 3637.95,3269 3477.95,3269 3457.95,3249
  region net NetC76_1: 4060,3419 4060,3239 4055,3234 4055,3161 4028,3161 4015,3174 3955,3174 3930,3199 3930,3419
  region net NetC121_2: 2580,3025 2630,2975 2630,2930 2670,2890 2670,2840 2645,2840 2645,2870 2630,2885 2515,2885 2505,2895 2505,3010 2520,3025
  region net +5.0V_WSH: 2505,3080 2505,3055 2525,3045 2600,3045 2620,3025 2685,3025 2685,3260 2525,3260 2505,3240
  pour cut-out: 3673.21,1101.67 3673,1101.46 3673,1072 3686.79,1085.79 3686.79,1101.67
  pour cut-out: 3886.71,1172.89 3907.05,1172.89 3907.05,1094.05 3901.44,1088.44 3706.44,1088.44 3700,1082 3690.57,1082 3686.79,1085.79 3686.79,1104.79 3690,1108 3705,1108 3708,1105 3756.6,1105 3759.7,1108.1 3769.3,1108.1 3776.4,1101 3819.6,1101 3826.7,1108.1 3835.3,1108.1 3843.4,1100 3881,1100 3888,1107 3888,1154.57 3884.39,1158.18 3884.39,1170.57
  pour cut-out: 3708.01,1041.56 3909.44,1041.56 3918,1041 3920,1041 3920,1024 3687,1024 3687,1035 3693,1041
  pour cut-out: 3920,1051 3915,1051 3915,1042.56 3913.72,1041.28 3919.72,1041.28 3920,1041
  text "4" at 802,134 h40
  text ".Layer_Name" at -243,-1588.49 h60

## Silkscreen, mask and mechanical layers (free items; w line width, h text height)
Top Overlay:
  circle w6: c3495,1488 r41.79
  circle w6: c3382,1489 r43.46
  circle w10: c3620,1162 r2
  lines w6: 1356.75,3590.58 1379.75,3590.58 ; 3412,1567 3413,1567 3454,1526 3454,1518
  text "+5V" at 6200,1740 h30
  text "+3.3V" at 6155,1630 h30
  text "+" at 6310,890 h60
  text "TIDA-00555" at 1187,580 h60
  text "REV:E2" at 1207,465 h60
  text ".Layer_Name" at -243,-1588.49 h40
Bottom Overlay:
  circle w6: c5262,577 r42.95
  lines w6: 468,3087 573,3087 583,3077 ; 726,3132 726,3133 746,3153 746,3242 ; 929,3100 949,3100 961,3112 ; 932,3143 946,3143 947,3143 961,3157 ; 1742,2997 1754,2997 1759,3002 1759,3013 ; 1974,3237 1974,3319 ; 2182.64,3295 2189.64,3302 2250,3302 2272,3324 2297,3324 ; 2498,3145 2533,3145 2578,3100 2621,3100 ; 2569.99,3156 2581.99,3144 2627,3144 ; 2622,2763 2634,2763 2656,2785 ; 2763,2865 2779,2865 2817,2827 ; 2995,3246 2995,3322 ; 3206,3316 3206,3374 3206,3418 3197,3409 3216,3409 3207,3418 ; 3719,3145 3751,3145 3763,3157 3763,3175 3756,3168 3772,3168 3765,3175 ; 4016,3361 4016,3416 3987,3445 ; 4237,3441 4250,3441 4261,3452 4253,3452 4262,3443 4262,3451 ; 746,3242 736,3232 755,3232 746,3241 746,3242 ; 1974,3319 1963,3308 1983,3308 1983,3310 1974,3319 ; 3987,3445 3987,3433 3999,3445 3987,3445
  text ".Layer_Name" at -243,-1588.49 h60
Top Paste:
  text ".Layer_Name" at -243,-1588.49 h60
Bottom Paste:
  text ".Layer_Name" at -243,-1588.49 h60
Top Solder:
  text ".Layer_Name" at -243,-1588.49 h60
  text ".Layer_Name" at -243,-1588.49 h60
Bottom Solder:
  region: 698.24,3941.76 391.76,3941.76 345,3895 345,3510 400,3455 650,3455 665,3470 665,3700 740,3775 740,3900
  region: 810,3915 810,3785 885,3710 885,3480 900,3465 1105,3465 1205,3565 1205,3890 1153.24,3941.76 836.76,3941.76
  region: 1521.76,3941.76 1465,3885 1465,3500 1520,3445 1770,3445 1785,3460 1785,3690 1860,3765 1860,3890 1808.24,3941.76
  region: 1920,3905 1920,3775 1995,3700 1995,3470 2010,3455 2090,3455 2145,3510 2290,3510 2315,3535 2315,3870 2245,3940 1958.52,3940 1956.76,3941.76
  region: 2950,3940 2680,3940 2615,3875 2615,3490 2670,3435 2920,3435 2935,3450 2935,3680 3010,3755 3010,3880
  region: 3120,3940 3400,3940 3470,3870 3470,3550 3435,3515 3175,3515 3150,3540 3150,3685 3075,3760 3075,3895
  text ".Layer_Name" at -243,-1588.49 h60
Drill Guide:
  text ".Layer_Name" at -243,-1588.49 h60
M1 Board Outline:
  the board outline again, w10
M2 Board Dimensions:
  rectangle: -820.5,-1015.5 -695.5,-890.5
  rectangle: -695.5,-1140.5 -320.5,-1015.5
  lines w7: -820.5,-1015.5 179.5,-1015.5 ; -695.5,-1140.5 -695.5,-890.5 ; -570.5,-1140.5 -570.5,-890.5 ; -320.5,-1140.5 -320.5,-890.5 ; -70.5,-1140.5 -70.5,-890.5 ; -820.5,-1140.5 179.5,-1140.5 179.5,-890.5 -820.5,-890.5 -820.5,-1140.5
  lines w10: -820.5,-1205.5 -820.5,-1185.5 ; -760.5,-1215.5 -820.5,-1195.5 ; -760.5,-1175.5 -820.5,-1195.5 ; -596.42,-1195.5 -820.5,-1195.5 ; -44.58,-1195.5 179.5,-1195.5 ; 119.5,-1215.5 179.5,-1195.5 ; 119.5,-1175.5 179.5,-1195.5 ; 179.5,-1205.5 179.5,-1185.5
  text "1000 (mil)" at -586.42,-1231.49 h60
M3 3D STEP Top:
  text ".Layer_Name" at -243,-1588.49 h60
M4 3D STEP Bottom:
  text ".Layer_Name" at -243,-1588.49 h60
M5 Assembly Top:
  circle w6: c5978,1390 r7
  circle w6: c5853,1385 r7
  circle w6: c5388,1390 r7
  circle w6: c5273,1385 r7
  circle w6: c4803,1380 r7
  circle w6: c4688,1380 r7
  circle w6: c2772,1346 r7
  circle w6: c2650,1343 r7
  circle w6: c1776,1380 r7
  circle w6: c1658,1382 r7
  circle w6: c712,1385 r7
  circle w6: c593,1387 r7
  circle w6: c6375,1515 r20
  circle w6: c5950.24,826 r16.76
  lines w6: 6320,1545 6320,1845 6420,1845 6420,1545 6320,1545
  lines w10: -1112,-1660.17 5488,-1660.17 ; -1112,-1456.83 5490,-1456.83 ; -1112,-1253.5 -1112,-1863.5 2893,-1863.5 5490,-1863.5 5490,-1253.5 -1111.5,-1253.5 -1111.5,-1863.5 464,-1863.5 ; 1353,-1863.5 1353,-1253.5 ; 2620,-1456.83 2620,-1253.5 ; 3460,-1456.83 3460,-1253.5 ; 4082,-1870 4082,-1667.17
  text "J28" at 6275,1870 h30
  text "TP12" at 3330,1548 h30
  text "TP11" at 3447,1548 h30
  text "COMPONENTS MARKED 'DNP' SHOULD NOT BE POPULATED." at 336.04,-1091.71 h30
  text "ASSEMBLY VARIANT:" at 335.54,-1207.21 h30
  text ".VariantName" at 1371.54,-1207.21 h30
  text "PCB VIEWED FROM TOP SIDE" at -1048.5,-1385.67 h30
  text "BOARD #:" at 1428,-1385.67 h30
  text "REV:" at 2818,-1385.67 h30
  text ".PCB_Rev" at 3109.5,-1385.67 h30
  text "SVN REV:" at 3656,-1385.67 h30
  text ".VersionControl_RevNumber" at 4162,-1385.67 h30
  text "TIDA-00555" at 1880,-1390 h30
  text "LAYER NAME =" at -1063,-1587 h30
  text "Top Assembly" at -237,-1606 h30
  text "PLOT NAME =" at -1048.5,-1794.34 h30
  text ".plot_File_Name" at -243,-1794.34 h30
  text "GENERATED    :" at 1430,-1794.34 h30
  text ".Print_Date" at 2299.5,-1794.34 h30
  text ".Print_Time" at 3028.5,-1794.34 h30
  text "TEXAS INSTRUMENTS" at 4293,-1794.34 h30
M6 Assembly Bottom:
  lines w10: -1112.5,-1457.33 5489.5,-1457.33 ; -1110.5,-1660.67 5489.5,-1660.67 ; 295.5,-1870.5 295.5,-1667.67 ; 917.5,-1457.33 917.5,-1254 ; 1757.5,-1457.33 1757.5,-1254 ; 3024.5,-1864 3024.5,-1254 ; 3913.5,-1864 5489,-1864 5489,-1254 -1112.5,-1254 -1112.5,-1864 1484.5,-1864 5489.5,-1864 5489.5,-1254
  text "C30" at 6255,1680 h30
  text "TP18" at 5315,645 h30
  text "COMPONENTS MARKED 'DNP' SHOULD NOT BE POPULATED." at 5282,-1048 h60
  text ".VariantName" at 4238,-1164 h60
  text "ASSEMBLY VARIANT:" at 5277,-1164 h60
  text ".VersionControl_RevNumber" at 215.5,-1386.17 h60
  text "SVN REV:" at 721.5,-1386.17 h60
  text ".PCB_Rev" at 1268,-1386.17 h60
  text "REV:" at 1559.5,-1386.17 h60
  text "TIDA-00555" at 2404,-1386.17 h60
  text "BOARD #:" at 2949.5,-1386.17 h60
  text "PCB VIEWED FROM BOTTOM SIDE" at 5426,-1386.17 h60
  text "Bottom Assembly" at 4702,-1584 h60
  text "LAYER NAME =" at 5443,-1585 h60
  text "TEXAS INSTRUMENTS" at 84.5,-1794.84 h60
  text ".Print_Time" at 1349,-1794.84 h60
  text ".Print_Date" at 2078,-1794.84 h40
  text "GENERATED    :" at 2947.5,-1794.84 h40
  text ".plot_File_Name" at 4620.5,-1794.84 h60
  text "PLOT NAME =" at 5426,-1794.84 h60
M7 LPKF Text Top:
  lines w10: 2830,-310 2830,1840 ; 3250,-395 3250,1710 ; 3350,-855 3350,1705 ; 4020,-850 4020,1715 ; 4120,-860 4120,1705 ; 4120,-780 4120,1785 ; 4220,-790 4220,1775 ; 4890,-900 4890,1710 ; 4890,-875 4890,1705 ; 4890,-765 4890,1800 ; 4990,-815 4990,1750 ; 4990,-775 4990,1790 ; 5090,-825 5090,1740 ; 5560,-895 5560,1710 ; 6208,-895 6208,1700
M9 Title Sheet:
  drawing of 57 lines, arcs and shapes, not listed
  text "1" at -80.16,7306.5 h70
  text "2" at 2415.5,7306.5 h70
  text "3" at 4904.84,7306.5 h70
  text "4" at 7411.51,7306.5 h70
  text "5" at 9910.5,7306.5 h70
  text "6" at 12415.5,7306.5 h70
  text "A" at -1236.5,6163.5 h70
  text "A" at 13563.5,6163.5 h70
  text "B" at -1236.5,3783.5 h70
  text "B" at 13563.5,3783.5 h70
  text "C" at -1236.5,1408.5 h70
  text "C" at 13563.5,1408.5 h70
  text "PROJECT TITLE:" at 10523.5,-452.5 h45
  text ".PRJ_Title" at 10573.5,-585.83 h70
  text "DESIGNED FOR:" at 10523.5,-753.5 h45
  text ".PRJ_Customer" at 10573.5,-893.5 h70
  text "D" at -1236.5,-961.5 h70
  text "D" at 13563.5,-961.5 h70
  text "FILE NAME:" at 10523.5,-1053.5 h45
  text ".prj_number" at 10573.5,-1173.5 h70
  text "Texas Instruments (TI) and/or its licensors do not warrant the accuracy or completeness of this specification" at 5554,-1335.34 h45
  text "ENGINEER:" at 10523.5,-1343.5 h45
  text "LAYOUT BY:" at 12028.5,-1343.5 h45
  text "or any information contained therein. TI and/or its licensors do not warrant that this design will meet" at 5509.01,-1448 h45
  text ".prj_engineer" at 10795,-1460 h70
  text "the specifications, will be suitable for your application or fit for any particular purpose, or will operate in" at 5509.01,-1560.67 h45
  text "ALTIUM DESIGNER VERSION:" at 12028.5,-1653.5 h45
  text "an implementation. TI and/or its licensors do not warrant that the design is production worthy. You should" at 5509.01,-1673.33 h45
  text "completely validate and test your design implementation to confirm the system functionality for your application." at 5554,-1786 h45
  text ".print_Scale" at 10573.5,-1786.83 h70
  text ".Application_BuildNumber" at 12079,-1786.83 h70
  text "1" at -80.16,-1993.5 h70
  text "2" at 2415.5,-1993.5 h70
  text "3" at 4904.84,-1993.5 h70
  text "4" at 7411.51,-1993.5 h70
  text "5" at 9910.5,-1993.5 h70
  text "6" at 12415.5,-1993.5 h70
M10 Fab Notes:
  drawing of 231 lines, arcs and shapes, not listed
  text "DESIGN INFORMATION" at 11561.02,6080 h60
  text "(REFER ALSO ARRAY/PANEL PROFILING INFORMATION)" at 11199.46,5918.29 h60
  text "BOARD SIZE" at 10513.46,5914 h60
  text "6490MIL" at 10975.78,5786.18 h60
  text "X" at 11481.46,5786.18 h60
  text "3985MIL" at 11712.78,5786.18 h60
  text "Number of Layers :" at 10916.46,5649 h60
  text "4" at 12011.27,5639 h60
  text "MIN. TRACK WIDTH:" at 10916.46,5510 h60
  text "8" at 12012.7,5510 h60
  text "MIL" at 12167.46,5510 h60
  text "MIN. CLEARANCE:" at 10916.46,5378 h60
  text "8" at 12012.7,5378 h60
  text "MIL" at 12167.46,5378 h60
  text "19.685" at 11880,5250 h60
  text "MIL" at 12240,5250 h60
  text "MIN. VIA PAD SIZE:" at 10916.46,5246 h60
  text "EXTERNAL" at 12572,5106 h60
  text "0.1499mm (5.9055MIL)" at 11611.46,5104.29 h60
  text "MINIMUM ANNULAR RING" at 10587.23,5100 h60
  text "PER" at 10787.23,4982 h60
  text "IPC-D-275 CLASS 2 LEVEL C" at 11007.23,4982 h60
  text "MIL, HOLES" at 12495.46,4869.71 h60
  text "+/-" at 12103,4869 h60
  text "+/-" at 12957,4869 h60
  text "REGISTRATION TOLERANCES:" at 10587.23,4864 h60
  text "METAL" at 11787,4864 h60
  text "5" at 12363.2,4864 h60
  text "3" at 13196.2,4864 h60
  text "MIL" at 13312.46,4864 h60
  text "MATERIAL:" at 10512.46,4594.54 h60
  text "FR-4 High Tg" at 11498.9,4454.21 h60
  text "X" at 11340,4447 h60
  text "FR-408" at 10933.46,4445.64 h60
  text "OTHER" at 12421.46,4445.64 h60
  text "63MIL (1.6mm) +/-10%" at 11253.56,4282.92 h60
  text "THICKNESS:" at 10587.23,4278.64 h60
  text "X" at 11125.4,4278.64 h60
  text "OTHER" at 12538.46,4278.64 h60
  text "TOLERANCE:" at 10587.23,4120.64 h60
  text "X" at 11426.53,4120.64 h60
  text "ANSI IPC-6012 TYPE 3 CLASS 2" at 11613.48,4120.64 h60
  text "OTHER +/-" at 11613.46,3964.64 h60
  text "BOW & TWIST:" at 10587.23,3807.64 h60
  text "X" at 11426.53,3807.64 h60
  text "ANSI IPC-6012 TYPE 3 CLASS 2" at 11613.48,3807.64 h60
  text "OTHER +/-" at 11613.46,3649.13 h60
  text "COPPER THICKNESS (FINISHED):" at 10512.46,3513.64 h60
  text "1.4MIL (1oz)" at 11392.46,3360.92 h60
  text "2MIL (1.4oz)" at 12159.46,3360.92 h60
  text "2.8MIL (2oz)" at 12886.46,3360.92 h60
  text "OUTER:" at 10869.46,3356.64 h60
  text "X" at 12760,3350 h60
  text "X" at 12035,3210 h60
  text "1.4MIL (1oz)" at 11392.46,3203.92 h60
  text "2.8MIL (2oz)" at 12159.46,3203.92 h60
  text "N/A" at 12886,3204.29 h60
  text "INNER SIGNAL:" at 10580.38,3199.64 h60
  text "DRILLING:" at 10512.46,3060.64 h60
  text "REFERENCE:" at 10587.23,2943.64 h60
  text "X" at 11235.46,2943.64 h60
  text "AS SHOWN" at 11422.46,2943.64 h60
  text "X" at 12136.46,2943.64 h60
  text "NC_DRILL FILES" at 12273.46,2943.64 h60
  text "PTH MIN COPPER THICKNESS:" at 10587.23,2785.64 h60
  text "X" at 11937.46,2785.64 h60
  text "1MIL" at 12074.46,2785.64 h60
  text "OTHER" at 12571.46,2785.64 h60
  text "BOARD FINISH:" at 10512.46,2626.64 h60
  text "SILKSCREEN:" at 10667.68,2508.64 h60
  text "X" at 11616.46,2508.64 h60
  text "TOP" at 11742.46,2508.64 h60
  text "X" at 12126.46,2508.64 h60
  text "BOTTOM" at 12253.46,2508.64 h60
  text "SILKSCREEN COLOR:" at 10667.68,2341.64 h60
  text "X" at 11615.42,2341.64 h60
  text "WHITE" at 11742.46,2341.64 h60
  text "OTHER" at 12253.46,2341.64 h60
  text "SOLDER RESIST COLOR:" at 10667.68,2171.64 h60
  text "X" at 11235.42,2012.44 h60
  text "GREEN" at 11362.46,2012.44 h60
  text "BLUE" at 11953.46,2012.44 h60
  text "OTHER" at 12491.46,2012.44 h60
  text "IMMERSION GOLD (ENIG)" at 11573.46,1823.92 h60
  text "ENEPIG" at 12911,1820.64 h60
  text "SURFACE FINISH:" at 10512.46,1819.64 h60
  text "X" at 11386.51,1819.64 h60
  text "IMM. TIN/SILVER OR EQUIV" at 10842,1662.64 h60
  text "OTHER" at 12273.46,1662.64 h60
  text "ARRAY/PANEL:" at 10512.46,1483.64 h60
  text "CUT AND TRIM PER MECH LAYER 1" at 11573.46,1479.35 h60
  text "N.C. ROUTE" at 11573.46,1327.64 h60
  text "X" at 12252.46,1327.64 h60
  text "V. SCORE" at 12439.46,1327.64 h60
  text "CERTIFICATION:" at 10512.46,1190.64 h60
  text "MATERIALS AND WORKMANSHIP FOR ALL PCBS" at 11237.46,1190.64 h60
  text "TO MEET OR EXCEED THE REQUIREMENTS OF:" at 11237.46,1092.64 h60
  text "X" at 10863.96,956.13 h60
  text "ANSI IPC-A-600F CLASS ->" at 11002.96,956.13 h60
  text "X" at 12642.02,956.13 h60
  text "2" at 12760.96,956.14 h60
  text "1" at 12445.96,954.64 h60
  text "3" at 13114.96,954.64 h60
  text "X" at 10866.02,796.64 h60
  text "UL 94V-0" at 11002.96,796.64 h60
  text "X" at 11678.02,796.64 h60
  text "RoHS" at 11814.96,796.64 h60
  text "OTHER" at 12459.36,796.64 h60
  text "PER ORDER" at 12856.42,796.64 h60
  text "ADDITIONAL REQUIREMENTS:" at 10512.46,655.64 h60
  text "NO" at 12880.58,655.54 h60
  text "VIA TENTING" at 11795.13,646 h60
  text "X" at 12364.85,643.83 h60
  text "YES" at 12479.11,640.44 h60
  text "MICROSECTION:" at 10587.23,540.64 h60
  text "YES" at 11492.96,540.64 h60
  text "IMPEDANCE CONTROL:" at 11753.13,516 h60
  text "YES" at 12745,515 h60
  text "X" at 13280,505 h60
  text "NO" at 13112.6,497.69 h60
  text "REQUIRED" at 12354.46,384.49 h60
  text "BARE BOARD ELEC. TEST:" at 10587.23,381.64 h60
  text "NONE" at 11892.96,381.64 h60
  text "X" at 12227.46,381.64 h60
  text "PER ORDER" at 12946.46,381.64 h60
  text "MANUFACTURER'S UL:" at 10587.23,224.64 h60
  text "RAIL" at 11752.96,220.35 h60
  text "METAL" at 12244.77,220.35 h60
  text "X" at 12620,220 h60
  text "SILK" at 12756.46,220.35 h60
M11 Gerber Information:
  lines w10: -1112,-1660.17 5488,-1660.17 ; -1112,-1456.83 5490,-1456.83 ; -1112,-1253.5 -1112,-1863.5 2893,-1863.5 5490,-1863.5 5490,-1253.5 -1111.5,-1253.5 -1111.5,-1863.5 464,-1863.5 ; 1353,-1863.5 1353,-1253.5 ; 2620,-1456.83 2620,-1253.5 ; 3460,-1456.83 3460,-1253.5 ; 4082,-1870 4082,-1667.17
  text "ALL ARTWORK VIEWED FROM TOP SIDE" at -1048.5,-1385.67 h60
  text "BOARD #:" at 1428,-1385.67 h60
  text "REV:" at 2818,-1385.67 h60
  text ".PCB_Rev" at 3109.5,-1385.67 h60
  text "SVN REV:" at 3656,-1385.67 h60
  text ".VersionControl_RevNumber" at 4162,-1385.67 h60
  text ".PRJ_Number" at 1880,-1390 h50
  text "LAYER NAME =" at -1048.5,-1588.49 h60
  text "PLOT NAME =" at -1048.5,-1794.34 h60
  text ".plot_File_Name" at -243,-1794.34 h60
  text "GENERATED    :" at 1430,-1794.34 h60
  text ".Print_Date" at 2299.5,-1794.34 h60
  text ".Print_Time" at 3028.5,-1794.34 h60
  text "TEXAS INSTRUMENTS" at 4293,-1794.34 h60
M12 Stackup:
  lines w6: 10545,6970.5 13420,6970.5 ; 10545,7083.1 13420,7083.1 ; 10485,6246 ccw(c10521,6246) 10521,6210 13444,6210 ccw(c13444,6246) 13480,6246 13480,7184 ccw(c13444,7184) 13444,7220 10521,7220 ccw(c10521,7184) 10485,7184 10485,6246
  text "Layer Stack Up Detail for: TIDA-00555 _E2.PcbDoc" at 10545,7112.95 h52
  text "Layer" at 10545,7041.1 h26
  text "Gerber" at 11551.14,7041.1 h26
  text "Copper" at 12211.52,7041.1 h26
  text "Dielectric" at 12914.35,7041.1 h26
  text "Name" at 10545,6989.1 h26
  text "Document" at 11551.14,6989.1 h26
  text "Thickness" at 12211.52,6989.1 h26
  text "Material" at 12914.35,6989.1 h26
  text "Top Solder Mask" at 10545,6914.9 h36
  text "(.GTS)" at 11551.14,6914.9 h36
  text "Solder Resist" at 12914.35,6914.9 h36
  text "Top Layer" at 10545,6809.69 h36
  text "(.GTL)" at 11551.14,6809.69 h36
  text "2.8mil" at 12211.52,6809.69 h36
  text "FR-4 High Tg" at 12914.35,6757.08 h36
  text "MidLayer1" at 10545,6704.48 h36
  text "(.G1)" at 11551.14,6704.48 h36
  text "2.8mil" at 12211.52,6704.48 h36
  text "FR-4 High Tg" at 12914.35,6651.88 h36
  text "MidLayer2" at 10545,6599.27 h36
  text "(.G2)" at 11551.14,6599.27 h36
  text "2.8mil" at 12211.52,6599.27 h36
  text "FR-4 High Tg" at 12914.35,6546.67 h36
  text "Bottom Layer" at 10545,6494.06 h36
  text "(.GBL)" at 11551.14,6494.06 h36
  text "2.8mil" at 12211.52,6494.06 h36
  text "Bottom Solder Mask" at 10545,6388.85 h36
  text "(.GBS)" at 11551.14,6388.85 h36
  text "Solder Resist" at 12914.35,6388.85 h36
M13 Component Bodies Top:
  text ".Layer_Name" at -243,-1588.49 h60
M14 Component Bodies Bottom:
  text ".Layer_Name" at -243,-1588.49 h60
M15 Courtyards Top:
  text ".Layer_Name" at -243,-1588.49 h60
M16 Courtyards Bottom:
  text ".Layer_Name" at -243,-1588.49 h60
Drill Drawing:
  text ".legend" at 2259,4881 h60
  text "Drill Table" at 2246,4691 h60
  text "FOR 7.874MIL DRILL +0/-7.874MIL" at 2245,4599 h60
  text "FOR 16MIL DRILL +0/-16MIL" at 2241,4493 h60
  text "FOR PTH DRILL +/-3MIL" at 2239,4375 h60
  text "FOR NPTH DRILL +/-2MIL" at 2238,4278 h60
  text ".Layer_Name" at -243,-1588.49 h60

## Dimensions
0,3985 to 6490,3985 on M2 Board Dimensions
196.85,196.85 to 0,0 on Drill Drawing
196.85,196.85 to 0,0 on Drill Drawing
6490,3985 to 6490,0 on M2 Board Dimensions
